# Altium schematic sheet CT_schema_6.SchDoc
size 297 x 173 mm
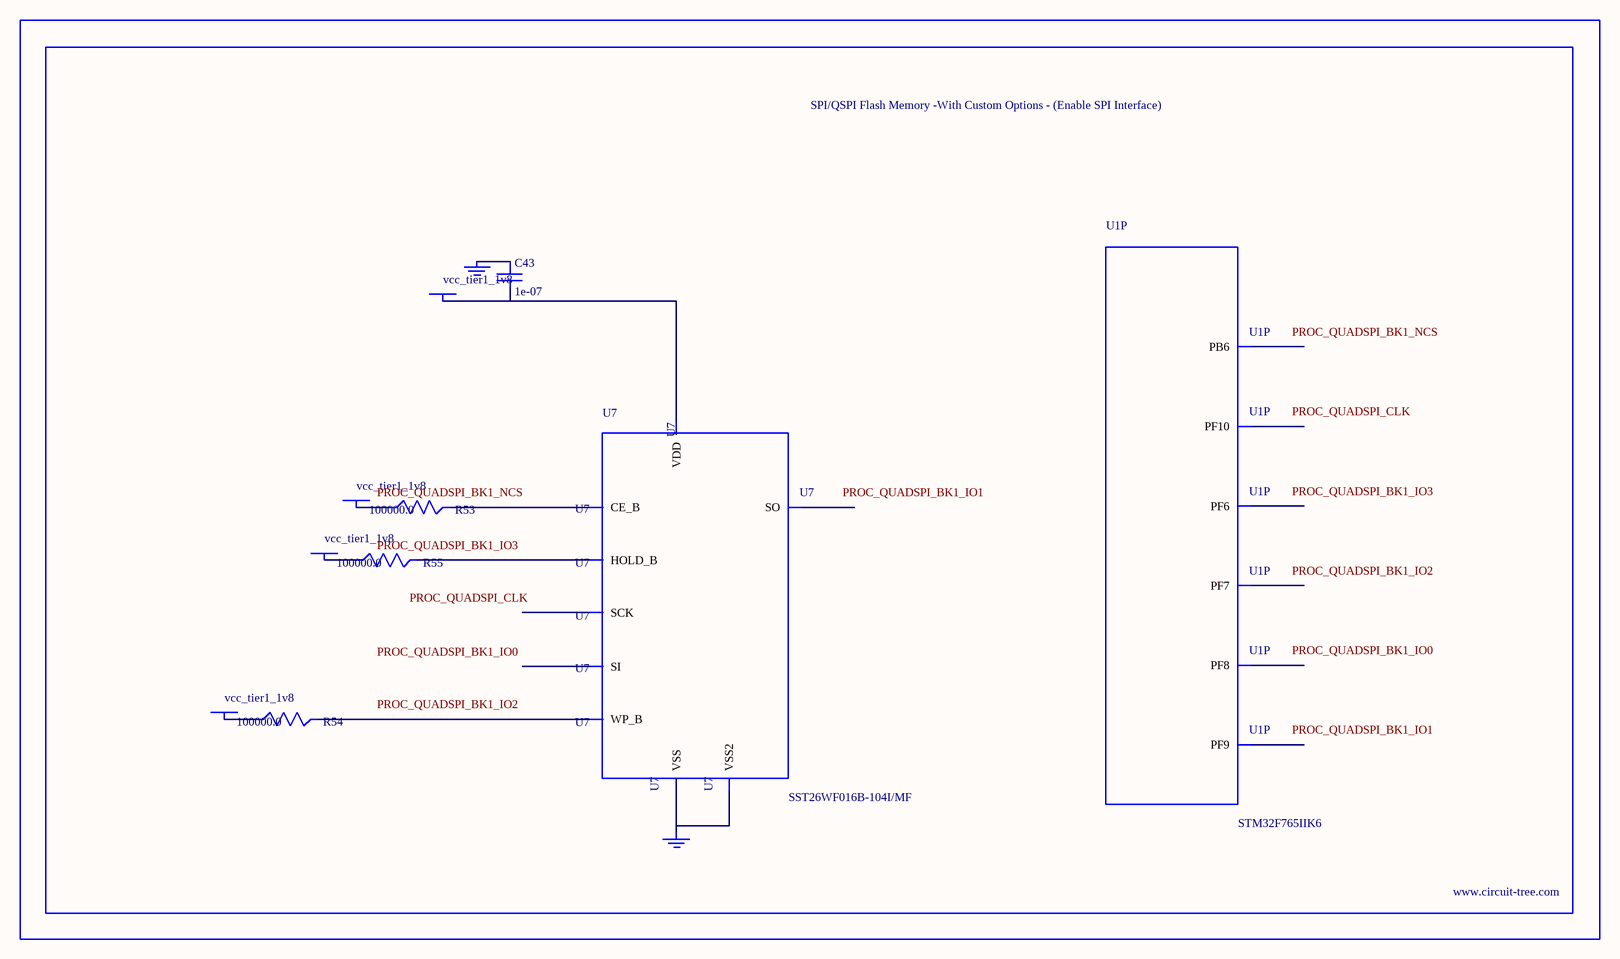
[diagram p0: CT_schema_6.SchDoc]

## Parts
BORDER5  (no value)
C43  1e-07  [C0402]
GND_INSTANCE_5_0  (no value)
GND_INSTANCE_5_1  (no value)
POWER_INSTANCE_5_0  vcc_tier1_1v8
POWER_INSTANCE_5_1  vcc_tier1_1v8
POWER_INSTANCE_5_2  vcc_tier1_1v8
POWER_INSTANCE_5_3  vcc_tier1_1v8
R53  100000.0  [R0603]
R54  100000.0  [R0603]
R55  100000.0  [R0603]
U1  STM32F765IIK6  [UFBGA176_25]  (part P of 17)
U7  SST26WF016B-104I/MF  [WFDN-8]

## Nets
NetC43_1: C43.1 GND_INSTANCE_5_0.0(GND)
NetC43_2: C43.2 POWER_INSTANCE_5_3.0(PWR) U7.8(VDD)
NetGND_INSTANCE_5_1_0: GND_INSTANCE_5_1.0(GND) U7.4(VSS) U7.9(VSS2)
NetPOWER_INSTANCE_5_0_0: POWER_INSTANCE_5_0.0(PWR) R53.1
NetPOWER_INSTANCE_5_1_0: POWER_INSTANCE_5_1.0(PWR) R54.1
NetPOWER_INSTANCE_5_2_0: POWER_INSTANCE_5_2.0(PWR) R55.1
NetR53_2: R53.2 U7.1(CE_B)
NetR54_2: R54.2 U7.3(WP_B)
NetR55_2: R55.2 U7.7(HOLD_B)

Not connected (* = marked no-connect by the designer): U1 B6(PB6) K1(PF7) K2(PF6) L1(PF10) L2(PF9) L3(PF8); U7 2(SO) 5(SI) 6(SCK)

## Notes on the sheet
- Labels drawn without touching a wire or pin: PROC_QUADSPI_BK1_IO0, PROC_QUADSPI_BK1_IO1, PROC_QUADSPI_BK1_IO2, PROC_QUADSPI_BK1_IO3, PROC_QUADSPI_BK1_NCS, PROC_QUADSPI_CLK

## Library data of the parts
BORDER5 = BORDER_PAGE5
C43 = C0402C104K3RACTU
GND_INSTANCE_5_0 GND_INSTANCE_5_1 = GND
POWER_INSTANCE_5_0-POWER_INSTANCE_5_3 = PWR
R53-R55 = RC0603JR-07100KL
